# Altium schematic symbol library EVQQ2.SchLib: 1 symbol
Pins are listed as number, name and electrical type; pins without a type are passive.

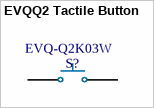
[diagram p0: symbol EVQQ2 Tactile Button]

## EVQQ2 Tactile Button
designator S?, comment Manufacturer Part Number: EVQ-Q2K03W  (hidden comment: EVQQ2)
EVQQ2 Tactile Button; Manufacturer: Panasonic Electronic Components; Circuit: SPST-NO; Switch Function: Off-Mom; Contact Rating @ Voltage: 0.02A @ 15VDC; Actuator Type: Standard; Actuator Height off PCB, from Pins: 3.10mm; Actuator Orientation: Top Actuated; Outline: 6.60mm x 6.00mm; Illumination: Non-Illuminated; Operating Force: 130gf; Switch Travel: 0.25mm; Mechanical Life: 1,000,000 Cycles
footprint EVQQ2 (Panasonic EVQQ2 Tactile Button)
pins: A, B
